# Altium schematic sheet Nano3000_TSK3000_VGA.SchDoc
size A3
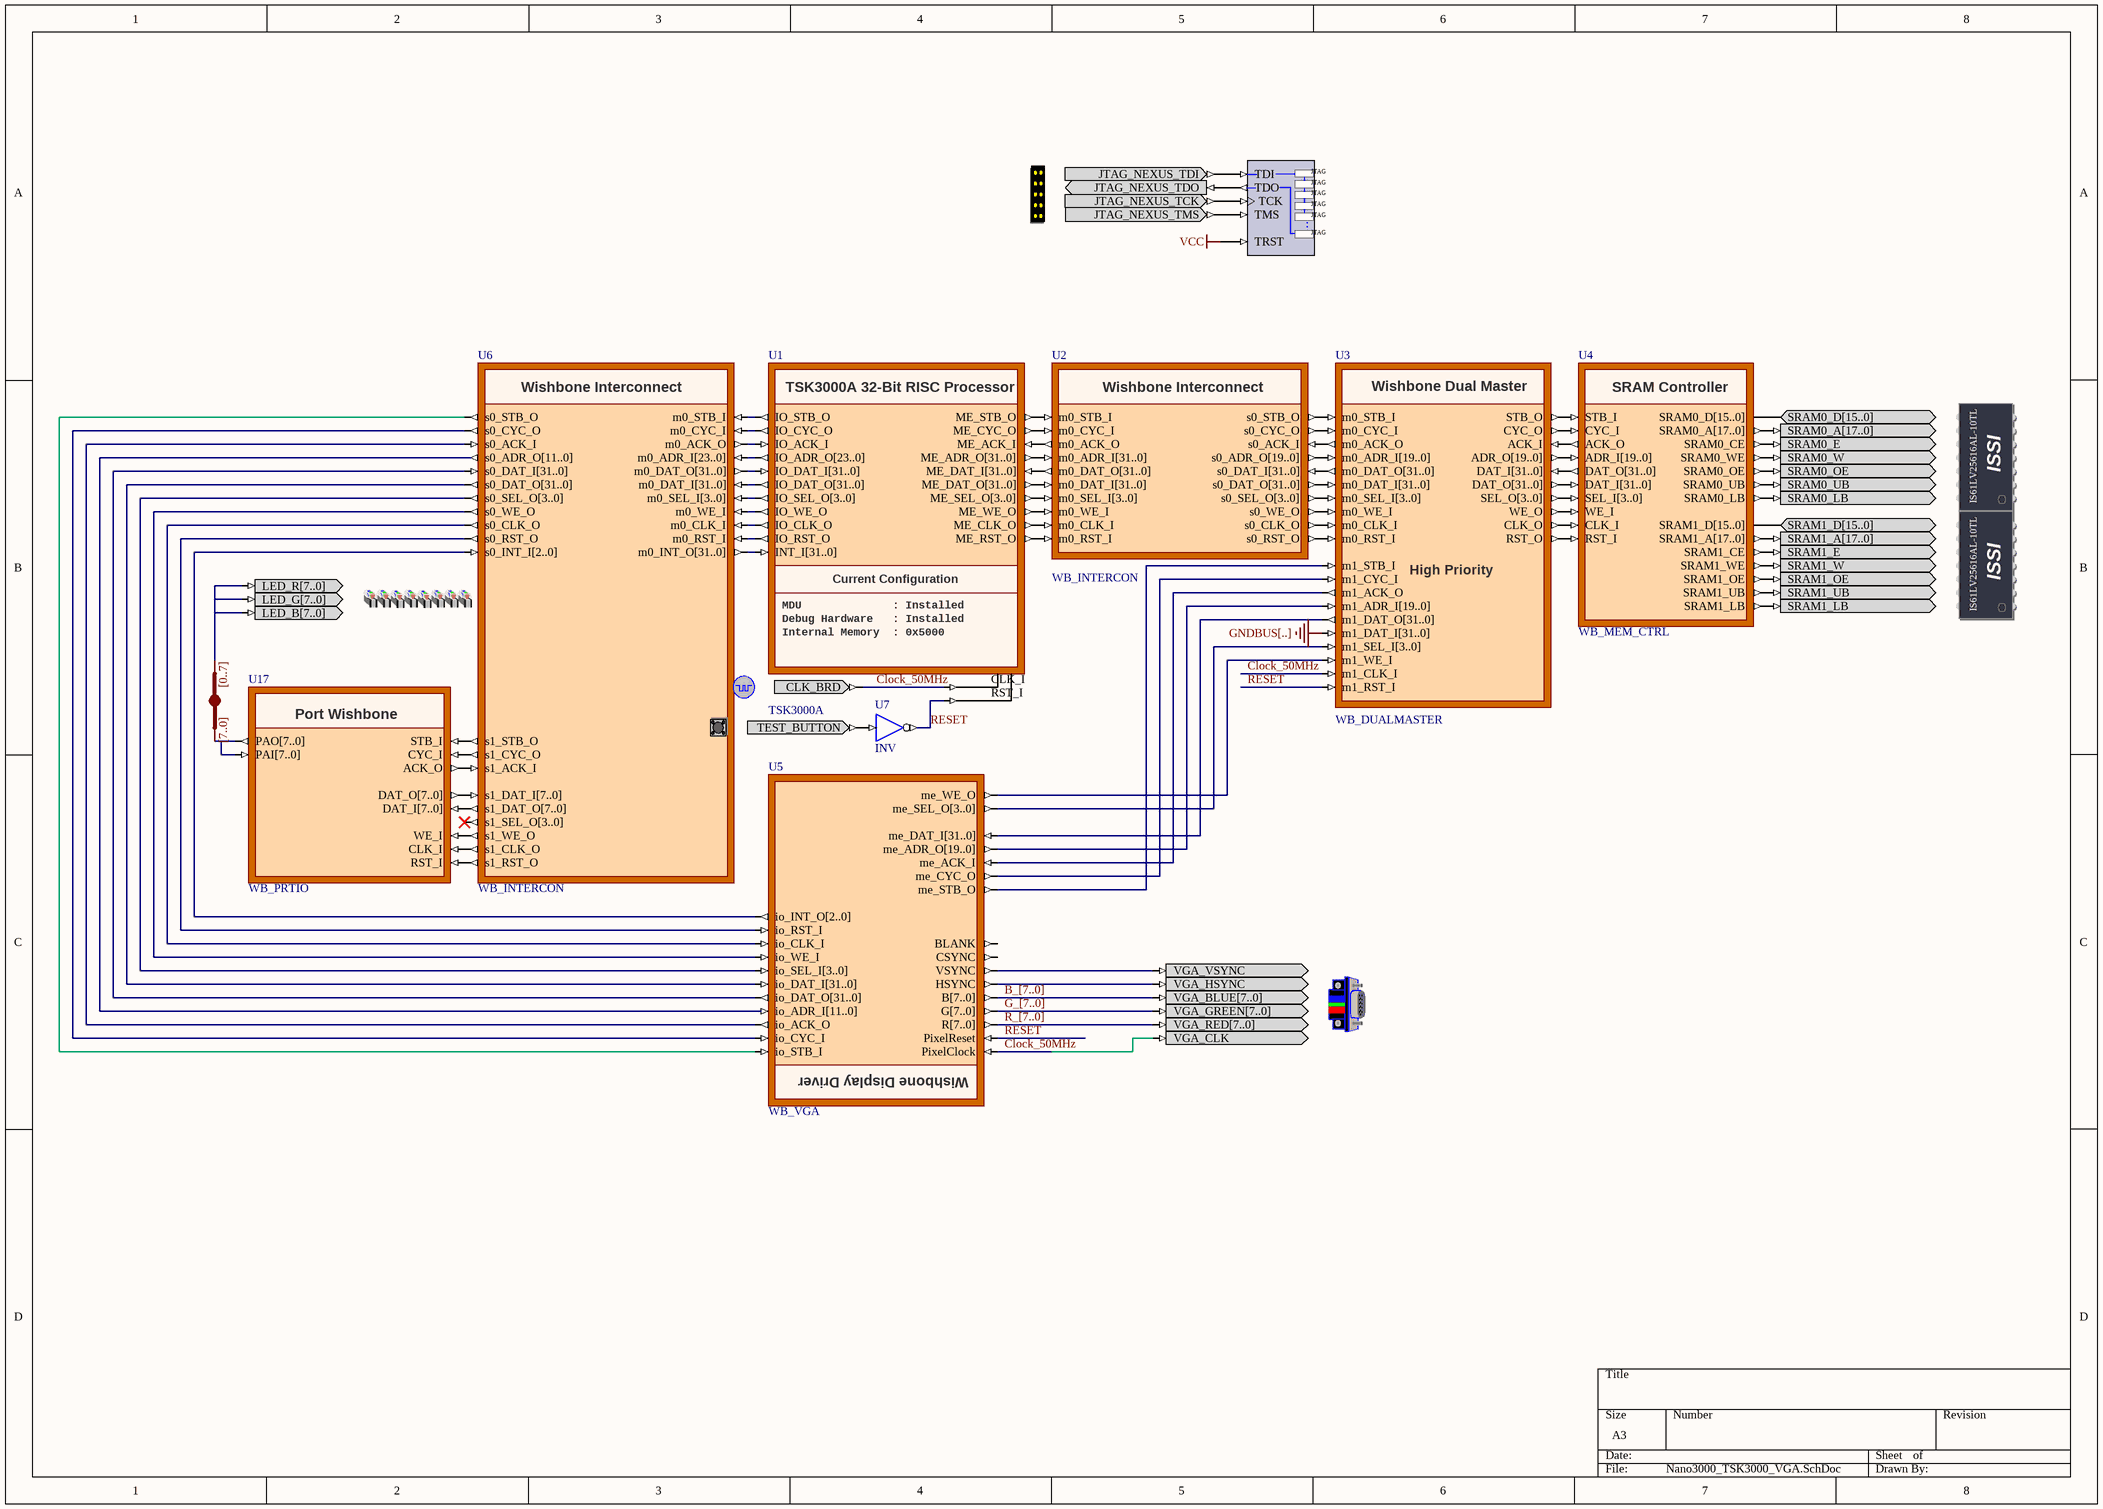
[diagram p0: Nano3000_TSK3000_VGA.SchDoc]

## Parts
(Parts that share a designator on the sheet are numbered #1, #2 ... from top to bottom, then left to right.)
?#1  NEXUS_JTAG_CONNECTOR  (value not drawn)
?#2  SRAM0  (value not drawn)
?#3  SRAM1  (value not drawn)
?#4  LEDS_RGB  (value not drawn)
?#5  CLOCK_BOARD  (value not drawn)
?#6  TEST_BUTTON  (value not drawn)
?#7  VGACNTR  (value not drawn)
JB_AUTO?  IndexA: [0..7]  IndexB: [7..0]  (hidden comment: JB)
NEXUS_JTAG_PORT  NEXUS_JTAG_PORT  (value not drawn)
U1  TSK3000A
U2  WB_INTERCON
U3  WB_DUALMASTER
U4  WB_MEM_CTRL
U5  WB_VGA
U6  WB_INTERCON
U7  INV
U17  WB_PRTIO

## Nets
GNDBUS[..]: U3.m1_DAT_I[31..0]
VCC: NEXUS_JTAG_PORT.TRST
Clock_50MHz: ?#5.CLK_BRD ?#7.VGA_CLK U1.CLK_I U3.m1_CLK_I U5.PixelClock
RESET: U1.RST_I U3.m1_RST_I U5.PixelReset U7.O
Net?#1_JTAG_NEXUS_TCK: ?#1.JTAG_NEXUS_TCK NEXUS_JTAG_PORT.TCK
Net?#1_JTAG_NEXUS_TDI: ?#1.JTAG_NEXUS_TDI NEXUS_JTAG_PORT.TDI
Net?#1_JTAG_NEXUS_TDO: ?#1.JTAG_NEXUS_TDO NEXUS_JTAG_PORT.TDO
Net?#1_JTAG_NEXUS_TMS: ?#1.JTAG_NEXUS_TMS NEXUS_JTAG_PORT.TMS
Net?#2_SRAM0_A[17..0]: ?#2.SRAM0_A[17..0] U4.SRAM0_A[17..0]
Net?#2_SRAM0_D[15..0]: ?#2.SRAM0_D[15..0] U4.SRAM0_D[15..0]
Net?#2_SRAM0_E: ?#2.SRAM0_E U4.SRAM0_CE
Net?#2_SRAM0_LB: ?#2.SRAM0_LB U4.SRAM0_LB
Net?#2_SRAM0_OE: ?#2.SRAM0_OE U4.SRAM0_OE
Net?#2_SRAM0_UB: ?#2.SRAM0_UB U4.SRAM0_UB
Net?#2_SRAM0_W: ?#2.SRAM0_W U4.SRAM0_WE
Net?#3_SRAM1_A[17..0]: ?#3.SRAM1_A[17..0] U4.SRAM1_A[17..0]
Net?#3_SRAM1_D[15..0]: ?#3.SRAM1_D[15..0] U4.SRAM1_D[15..0]
Net?#3_SRAM1_E: ?#3.SRAM1_E U4.SRAM1_CE
Net?#3_SRAM1_LB: ?#3.SRAM1_LB U4.SRAM1_LB
Net?#3_SRAM1_OE: ?#3.SRAM1_OE U4.SRAM1_OE
Net?#3_SRAM1_UB: ?#3.SRAM1_UB U4.SRAM1_UB
Net?#3_SRAM1_W: ?#3.SRAM1_W U4.SRAM1_WE
Net?#6_TEST_BUTTON: ?#6.TEST_BUTTON U7.I
Net?#7_VGA_HSYNC: ?#7.VGA_HSYNC U5.HSYNC
Net?#7_VGA_VSYNC: ?#7.VGA_VSYNC U5.VSYNC
NetU1_IO_ACK_I: U1.IO_ACK_I U6.m0_ACK_O
NetU1_IO_CLK_O: U1.IO_CLK_O U6.m0_CLK_I
NetU1_IO_CYC_O: U1.IO_CYC_O U6.m0_CYC_I
NetU1_IO_RST_O: U1.IO_RST_O U6.m0_RST_I
NetU1_IO_STB_O: U1.IO_STB_O U6.m0_STB_I
NetU1_IO_WE_O: U1.IO_WE_O U6.m0_WE_I
NetU1_ME_ACK_I: U1.ME_ACK_I U2.m0_ACK_O
NetU1_ME_ADR_O[31..0]: U1.ME_ADR_O[31..0] U2.m0_ADR_I[31..0]
NetU1_ME_CLK_O: U1.ME_CLK_O U2.m0_CLK_I
NetU1_ME_CYC_O: U1.ME_CYC_O U2.m0_CYC_I
NetU1_ME_DAT_I[31..0]: U1.ME_DAT_I[31..0] U2.m0_DAT_O[31..0]
NetU1_ME_DAT_O[31..0]: U1.ME_DAT_O[31..0] U2.m0_DAT_I[31..0]
NetU1_ME_RST_O: U1.ME_RST_O U2.m0_RST_I
NetU1_ME_SEL_O[3..0]: U1.ME_SEL_O[3..0] U2.m0_SEL_I[3..0]
NetU1_ME_STB_O: U1.ME_STB_O U2.m0_STB_I
NetU1_ME_WE_O: U1.ME_WE_O U2.m0_WE_I
NetU2_s0_ACK_I: U2.s0_ACK_I U3.m0_ACK_O
NetU2_s0_ADR_O[19..0]: U2.s0_ADR_O[19..0] U3.m0_ADR_I[19..0]
NetU2_s0_CLK_O: U2.s0_CLK_O U3.m0_CLK_I
NetU2_s0_CYC_O: U2.s0_CYC_O U3.m0_CYC_I
NetU2_s0_DAT_I[31..0]: U2.s0_DAT_I[31..0] U3.m0_DAT_O[31..0]
NetU2_s0_DAT_O[31..0]: U2.s0_DAT_O[31..0] U3.m0_DAT_I[31..0]
NetU2_s0_RST_O: U2.s0_RST_O U3.m0_RST_I
NetU2_s0_SEL_O[3..0]: U2.s0_SEL_O[3..0] U3.m0_SEL_I[3..0]
NetU2_s0_STB_O: U2.s0_STB_O U3.m0_STB_I
NetU2_s0_WE_O: U2.s0_WE_O U3.m0_WE_I
NetU3_ACK_I: U3.ACK_I U4.ACK_O
NetU3_ADR_O[19..0]: U3.ADR_O[19..0] U4.ADR_I[19..0]
NetU3_CLK_O: U3.CLK_O U4.CLK_I
NetU3_CYC_O: U3.CYC_O U4.CYC_I
NetU3_DAT_I[31..0]: U3.DAT_I[31..0] U4.DAT_O[31..0]
NetU3_DAT_O[31..0]: U3.DAT_O[31..0] U4.DAT_I[31..0]
NetU3_m1_ACK_O: U3.m1_ACK_O U5.me_ACK_I
NetU3_m1_CYC_I: U3.m1_CYC_I U5.me_CYC_O
NetU3_m1_STB_I: U3.m1_STB_I U5.me_STB_O
NetU3_m1_WE_I: U3.m1_WE_I U5.me_WE_O
NetU3_RST_O: U3.RST_O U4.RST_I
NetU3_SEL_O[3..0]: U3.SEL_O[3..0] U4.SEL_I[3..0]
NetU3_STB_O: U3.STB_O U4.STB_I
NetU3_WE_O: U3.WE_O U4.WE_I
NetU5_io_ACK_O: U5.io_ACK_O U6.s0_ACK_I
NetU5_io_CLK_I: U5.io_CLK_I U6.s0_CLK_O
NetU5_io_CYC_I: U5.io_CYC_I U6.s0_CYC_O
NetU5_io_RST_I: U5.io_RST_I U6.s0_RST_O
NetU5_io_STB_I: U5.io_STB_I U6.s0_STB_O
NetU5_io_WE_I: U5.io_WE_I U6.s0_WE_O
NetU6_s1_ACK_I: U6.s1_ACK_I U17.ACK_O
NetU6_s1_CLK_O: U6.s1_CLK_O U17.CLK_I
NetU6_s1_CYC_O: U6.s1_CYC_O U17.CYC_I
NetU6_s1_DAT_I[7..0]: U6.s1_DAT_I[7..0] U17.DAT_O[7..0]
NetU6_s1_DAT_O[7..0]: U6.s1_DAT_O[7..0] U17.DAT_I[7..0]
NetU6_s1_RST_O: U6.s1_RST_O U17.RST_I
NetU6_s1_STB_O: U6.s1_STB_O U17.STB_I
NetU6_s1_WE_O: U6.s1_WE_O U17.WE_I

Not connected (* = marked no-connect by the designer): ?#4 LED_B[7..0] LED_G[7..0] LED_R[7..0]; ?#7 VGA_BLUE[7..0] VGA_GREEN[7..0] VGA_RED[7..0]; JB_AUTO? A[0..0] B[0..0]; U1 INT_I[31..0] IO_ADR_O[23..0] IO_DAT_I[31..0] IO_DAT_O[31..0] IO_SEL_O[3..0]; U3 m1_ADR_I[19..0] m1_DAT_O[31..0] m1_SEL_I[3..0]; U5 B[7..0] BLANK CSYNC G[7..0] io_ADR_I[11..0] io_DAT_I[31..0] io_DAT_O[31..0] io_INT_O[2..0] io_SEL_I[3..0] me_ADR_O[19..0] me_DAT_I[31..0] me_SEL_O[3..0] R[7..0]; U6 m0_ADR_I[23..0] m0_DAT_I[31..0] m0_DAT_O[31..0] m0_INT_O[31..0] m0_SEL_I[3..0] s0_ADR_O[11..0] s0_DAT_I[31..0] s0_DAT_O[31..0] s0_INT_I[2..0] s0_SEL_O[3..0] s1_SEL_O[3..0]*; U17 PAI[7..0] PAO[7..0]

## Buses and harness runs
bus B_[7..0]
bus G_[7..0]
bus R_[7..0]

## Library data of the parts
?#1 = NEXUS_JTAG_CONNECTOR: JTAG Port; PortComponent: True
?#2 = SRAM0: Free Static RAM - Daughterboard; PortComponent: True
?#3 = SRAM1: Free Static RAM - Daughterboard; PortComponent: True
?#4 = LEDS_RGB: LEDS RGB; PortComponent: True
?#5 = CLOCK_BOARD: Global System Clock Supply; PortComponent: True
?#6 = TEST_BUTTON: Test / Reset Button; PortComponent: True
?#7 = VGACNTR: VGA Dsub-15-Female-HD; PortComponent: True
JB_AUTO? = JB: System BUS Joiner
NEXUS_JTAG_PORT = NEXUS_JTAG_PORT: Soft Nexus-Chain Connector; NEXUS_JTAG_CONNECTOR: True; FunctionalClass: JTAG
U1 = TSK3000A: TSK3000A OCD Microprocessor; Nexus_JTAG_Device: True; Nexus_Core: Processor_OCDS; Nexus_JTAG_Order: 0; ConfigurationParameters: {}Version[1.1]{}Option_Processor[0]{}Option_Memory[4]{}Option_ExactMemory[20k]{}Option_MDU[0]{}Option_OCDS[0]{}Option_Shifter[0]{}Option_InterruptCount[32]{}Option_DebugWhenReset[0]{}; ConfiguratorName: FPGA_MCU32; Memory_Configuration: Record[AUTOIMPORT]{}AutoImport_Memory[False]{}AutoImport_Peripherals[False]{n}Record[CODE_EXPORT]{}ExportType[1]{n}Record[NEXUS_CORE]{}ComponentDesignator[Daughter_SRAM]{}Memory_Depth[0x200000]{}Memory_UsageType[ram]{}Memory_Speed[1]{}ProgramDownloadAddress[0x1000000]{}Memory_BusType[TSK3000:addr_bus]{}Memory_Mau[0x00000008]{}Memory_MatchedComponent[]{}Memory_Description[U2]{}Memory_FillBitPattern[]{}Memory_IncludeDependencies[False]{}Memory_ByLoadAddress[False]{}Memory_CopyDuringInit[False]{}Memory_NoCopyDuringInit[False]{}Memory_Interrupts[]{n}Record[NEXUS_CORE]{}ComponentDesignator[U1]{}Memory_Depth[20480]{}Memory_UsageType[nvram]{}Memory_Speed[1]{}ProgramDownloadAddress[0x00000000]{}Memory_BusType[TSK3000:addr_bus]{}Memory_Mau[0x00000008]{}Memory_MatchedComponent[]{}Memory_Description[]{}Memory_FillBitPattern[]{}Memory_IncludeDependencies[False]{}Memory_ByLoadAddress[False]{}Memory_CopyDuringInit[False]{}Memory_NoCopyDuringInit[False]{}Memory_Interrupts[]{n}Record[PERIPHERAL]{}ComponentDesignator[LED_IO]{}Memory_Depth[0x0001]{}Memory_UsageType[peripheral]{}Memory_Speed[1]{}ProgramDownloadAddress[0xFF200000]{}Memory_BusType[TSK3000:addr_bus]{}Memory_Mau[8]{}Memory_MatchedComponent[]{}Memory_Description[U6]{}Memory_FillBitPattern[]{}Memory_IncludeDependencies[False]{}Memory_ByLoadAddress[False]{}Memory_CopyDuringInit[False]{}Memory_NoCopyDuringInit[False]{}Memory_Interrupts[]{n}Record[PERIPHERAL]{}ComponentDesignator[VGA_IO]{}Memory_Depth[0x1000]{}Memory_UsageType[peripheral]{}Memory_Speed[1]{}ProgramDownloadAddress[0xFF100000]{}Memory_BusType[TSK3000:addr_bus]{}Memory_Mau[8]{}Memory_MatchedComponent[]{}Memory_Description[U6]{}Memory_FillBitPattern[]{}Memory_IncludeDependencies[False]{}Memory_ByLoadAddress[False]{}Memory_CopyDuringInit[False]{}Memory_NoCopyDuringInit[False]{}Memory_Interrupts[29,30,31]{n}Record[PHYSICAL_MEMORY]{}ComponentDesignator[Daughter_SRAM]{}Memory_Depth[0x200000]{}Memory_UsageType[ram]{}Memory_Speed[1]{}ProgramDownloadAddress[0x1000000]{}Memory_BusType[TSK3000:addr_bus]{}Memory_Mau[0x00000008]{}Memory_MatchedComponent[]{}Memory_Description[U2]{}Memory_FillBitPattern[]{}Memory_IncludeDependencies[False]{}Memory_ByLoadAddress[False]{}Memory_CopyDuringInit[False]{}Memory_NoCopyDuringInit[False]{}Memory_Interrupts[]{n}Record[PHYSICAL_MEMORY]{}ComponentDesignator[U1]{}Memory_Depth[20480]{}Memory_UsageType[nvram]{}Memory_Speed[1]{}ProgramDownloadAddress[0x00000000]{}Memory_BusType[TSK3000:addr_bus]{}Memory_Mau[0x00000008]{}Memory_MatchedComponent[]{}Memory_Description[]{}Memory_FillBitPattern[]{}Memory_IncludeDependencies[False]{}Memory_ByLoadAddress[False]{}Memory_CopyDuringInit[False]{}Memory_NoCopyDuringInit[False]{}Memory_Interrupts[]{n}; ChildModel1: TSK3000A_MCU; ChildModel2: TSK3000A_MDU; ChildModel3: TSK3000A_OCDS; ChildModel4: TSK3000A_Shift_Barrel; ChildModel5: TSK3000A_Shift_Sequential; ChildModel6: Mult_32x32; ChildModel7: m33x33
U2 = WB_INTERCON: Configurable Wishbone Interconnect; ConfigurationParameters: {}Version[1.0]{}UnusedInterrupts[2]{}MasterAddressBits[0]{}Name0[Daughter_SRAM]{}Kind0[2]{}SpaceAfter0[14]{}Address_Base0[16777216]{}Address_Bits0[20]{}Address_Mode0[1]{}Address_DecodeWidth0[8]{}DataWidth0[0]{}UsedInterrupts0[ ]
U3 = WB_DUALMASTER: Configurable Wishbone Dual Master; ConfigurationParameters: {}Version[1.0]{}DataWidth[0]{}AddressWidth[20]{}SpaceAfter[2]{}DualType[1]{}PriorityDevice[1]
U4 = WB_MEM_CTRL: Configurable Memory Controller; ConfigurationParameters: {}Version[2.0]{}Option_MemoryType[Asynchronous SRAM]{}Option_MemorySize[1 MB (256K x 32-bit)]{}Option_Layout[2 x 16-bit Wide Devices]{}Option_Read[2]{}Option_WriteSetup[1]{}Option_WritePulse[1]{}Option_WriteHold[1]{}Option_FlashRead[4]{}Option_FlashWriteSetup[1]{}Option_FlashWritePulse[5]{}Option_FlashWriteHold[1]{}Option_SdramKeepRowOpen[0]{}Option_SdramClock[100]{}Option_SdramWriteRecovery[3]{}Option_SdramAutoRefresh[7]{}Option_SdramActiveToReadWrite[2]{}Option_SdramPrecharge[2]{}Option_SdramCasLatency[3]{}Option_SdramClockScheme[0]{}Option_SdramModeRegister[2]{}Option_SdramCache[True]{}Option_SdramRefreshTime[0]{}; UseInDSF: True
U5 = VGA32: Wishbone Display Driver; UseInDSF: True; ConfigurationParameters: {}Version[1.0]{}VgaKind[VGA32]{}Orientation[Right]{}ExtraSpace[1]{}AddressWidth[20]{}
U6 = WB_INTERCON: Configurable Wishbone Interconnect; ConfigurationParameters: {}Version[1.0]{}UnusedInterrupts[1]{}MasterAddressBits[1]{}Name0[VGA_IO]{}Kind0[0]{}SpaceAfter0[14]{}Address_Base0[1048576]{}Address_Bits0[12]{}Address_Mode0[0]{}Address_DecodeWidth0[8]{}DataWidth0[0]{}UsedInterrupts0[29,30,31]{}Name1[LED_IO]{}Kind1[0]{}SpaceAfter1[4]{}Address_Base1[2097152]{}Address_Bits1[0]{}Address_Mode1[1]{}Address_DecodeWidth1[8]{}DataWidth1[2]{}UsedInterrupts1[ ]
U7 = INV: Inverter; FunctionalClass: Logic Primitive; ArchiveName: GENERIC; VHDLIB_SIM: GENERIC_LIB
U17 = WB_PRTIO: Configurable Port Wishbone; UseInDSF: True; ConfigurationParameters: {}Version[2.0]{}Signal0Name[PA]{}Signal0Type[In/Out]{}Signal0BusString[{1}7..0{2}]{}Signal0Address[0]{}Signal0SpaceAfter[2]{}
